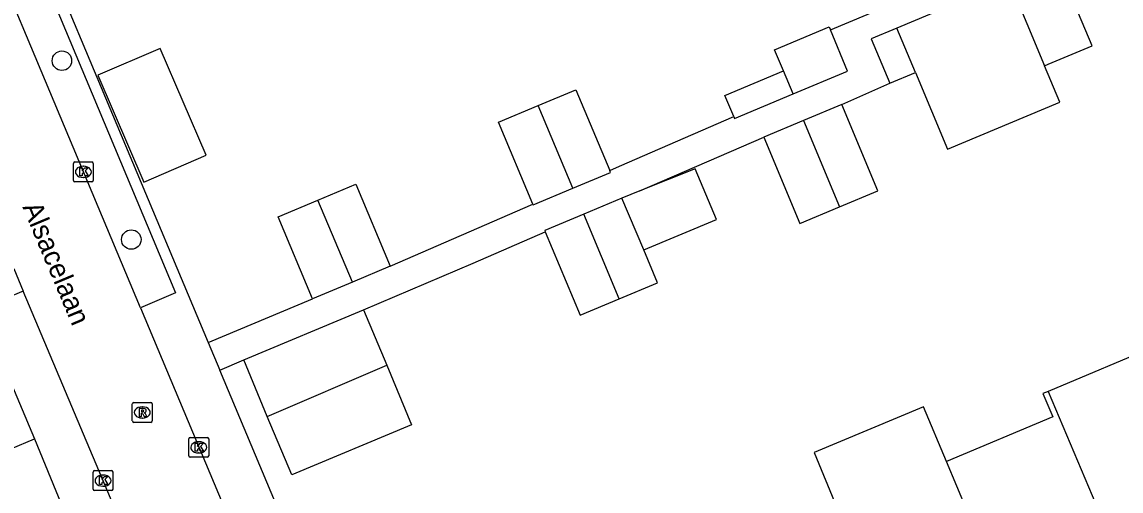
# Model space of a CAD drawing. Extents: x 157767 to 159171, y 387842 to 389425.
# Drawn here: x 158884.5 to 158939.7, y 388284.7 to 388308.2 of the extents above; entities that cross this region are included whole.
import ezdxf

# ---------------------------------------------------------------- set-up
doc = ezdxf.new("R2010")
doc.units = 0
for name, color, linetype in [('IMGEO_Boom', 7, 'Continuous'), ('IMGEO_Kolk', 7, 'Continuous'), ('IMGEO_Openbare_ruimte_label', 7, 'Continuous'), ('IMGEO_Pand', 7, 'Continuous'), ('IMGEO_Rijbaan_lokaal_open', 7, 'Continuous'), ('IMGEO_Rioolput', 7, 'Continuous'), ('IMGEO_Voetpad_open', 7, 'Continuous')]:
    doc.layers.add(name, color=color, linetype=linetype)

msp = doc.modelspace()

# ---------------------------------------------------------------- linework, layer by layer
at = {"layer": 'IMGEO_Boom'}
for centre in [(158886.479, 388306.281), (158889.962, 388297.308)]:
    msp.add_circle(centre, 0.489, dxfattribs=at)
at = {"layer": 'IMGEO_Kolk'}
for p, q in [((158887.054, 388300.278), (158887.054, 388301.13)), ((158887.129, 388301.204), (158887.981, 388301.204)), ((158887.542, 388300.984), (158887.567, 388300.984)), ((158888.055, 388301.13), (158888.055, 388300.278)), ((158887.565, 388300.424), (158887.54, 388300.424)), ((158887.981, 388300.204), (158887.129, 388300.204)), ((158892.847, 388286.46), (158892.847, 388287.312)), ((158892.922, 388287.386), (158893.774, 388287.386)), ((158893.335, 388287.166), (158893.36, 388287.166)), ((158893.848, 388287.312), (158893.848, 388286.46)), ((158893.358, 388286.606), (158893.333, 388286.606)), ((158893.774, 388286.386), (158892.922, 388286.386)), ((158888.042, 388284.789), (158888.042, 388285.641)), ((158888.117, 388285.715), (158888.969, 388285.715)), ((158888.53, 388285.495), (158888.555, 388285.495)), ((158889.043, 388285.641), (158889.043, 388284.789)), ((158888.553, 388284.935), (158888.528, 388284.935)), ((158888.969, 388284.715), (158888.117, 388284.715))]:
    msp.add_line(p, q, dxfattribs=at)
for points in [[(158887.054, 388300.278), (158887.054, 388301.13)], [(158887.129, 388301.204), (158887.981, 388301.204)], [(158887.375, 388300.904), (158887.498, 388300.904), (158887.498, 388300.753), (158887.628, 388300.904), (158887.792, 388300.904), (158887.646, 388300.753), (158887.799, 388300.504), (158887.647, 388300.504), (158887.562, 388300.668), (158887.498, 388300.601), (158887.498, 388300.504), (158887.375, 388300.504), (158887.375, 388300.904)], [(158888.055, 388301.13), (158888.055, 388300.278)], [(158887.981, 388300.204), (158887.129, 388300.204)], [(158892.847, 388286.46), (158892.847, 388287.312)], [(158892.922, 388287.386), (158893.774, 388287.386)], [(158893.168, 388287.086), (158893.291, 388287.086), (158893.291, 388286.935), (158893.421, 388287.086), (158893.585, 388287.086), (158893.439, 388286.935), (158893.592, 388286.686), (158893.44, 388286.686), (158893.355, 388286.85), (158893.291, 388286.783), (158893.291, 388286.686), (158893.168, 388286.686), (158893.168, 388287.086)], [(158893.848, 388287.312), (158893.848, 388286.46)], [(158893.774, 388286.386), (158892.922, 388286.386)], [(158888.042, 388284.789), (158888.042, 388285.641)], [(158888.117, 388285.715), (158888.969, 388285.715)], [(158888.363, 388285.415), (158888.486, 388285.415), (158888.486, 388285.264), (158888.616, 388285.415), (158888.78, 388285.415), (158888.634, 388285.264), (158888.787, 388285.015), (158888.635, 388285.015), (158888.55, 388285.179), (158888.486, 388285.112), (158888.486, 388285.015), (158888.363, 388285.015), (158888.363, 388285.415)], [(158889.043, 388285.641), (158889.043, 388284.789)], [(158888.969, 388284.715), (158888.117, 388284.715)]]:
    msp.add_lwpolyline(points, dxfattribs=at)
for centre, start, end in [((158887.131, 388301.128), 91.552, 178.448), ((158887.131, 388301.128), 91.552, 178.448), ((158887.979, 388301.128), 1.552, 88.448), ((158887.979, 388301.128), 1.552, 88.448), ((158887.131, 388300.28), 181.552, 268.448), ((158887.131, 388300.28), 181.552, 268.448), ((158887.979, 388300.28), 271.552, 358.448), ((158887.979, 388300.28), 271.552, 358.448), ((158892.924, 388287.31), 91.552, 178.448), ((158892.924, 388287.31), 91.552, 178.448), ((158893.772, 388287.31), 1.552, 88.448), ((158893.772, 388287.31), 1.552, 88.448), ((158892.924, 388286.462), 181.552, 268.448), ((158892.924, 388286.462), 181.552, 268.448), ((158893.772, 388286.462), 271.552, 358.448), ((158893.772, 388286.462), 271.552, 358.448), ((158888.119, 388285.639), 91.552, 178.448), ((158888.119, 388285.639), 91.552, 178.448), ((158888.967, 388285.639), 1.552, 88.448), ((158888.967, 388285.639), 1.552, 88.448), ((158888.119, 388284.791), 181.552, 268.448), ((158888.119, 388284.791), 181.552, 268.448), ((158888.967, 388284.791), 271.552, 358.448), ((158888.967, 388284.791), 271.552, 358.448)]:
    msp.add_arc(centre, 0.0765, start, end, dxfattribs=at)
for centre, major_axis, ratio, start_param, end_param in [((158887.541, 388300.704), (-0.387, 0.002), 0.722429, 4.712389, 7.853982), ((158887.566, 388300.704), (-0.39, 0.002), 0.717154, 1.570796, 4.712389), ((158893.334, 388286.886), (-0.387, 0.002), 0.722429, 4.712389, 7.853982), ((158893.359, 388286.886), (-0.39, 0.002), 0.717154, 1.570796, 4.712389), ((158888.529, 388285.215), (-0.387, 0.002), 0.722429, 4.712389, 7.853982), ((158888.554, 388285.215), (-0.39, 0.002), 0.717154, 1.570796, 4.712389)]:
    msp.add_ellipse(centre, major_axis=major_axis, ratio=ratio, start_param=start_param, end_param=end_param, dxfattribs=at)
at = {"layer": 'IMGEO_Pand'}
for points in [[(158935.815, 388306.03), (158935.99, 388306.103), (158938.199, 388307.027), (158936.419, 388311.28)], [(158934.036, 388310.282), (158928.398, 388307.923)], [(158934.036, 388310.282), (158935.815, 388306.03)], [(158922.702, 388305.775), (158922.262, 388306.827), (158925.004, 388307.974), (158925.064, 388307.831)], [(158923.187, 388304.617), (158925.929, 388305.764), (158925.064, 388307.831)], [(158928.398, 388307.923), (158927.106, 388307.383), (158928.041, 388305.15)], [(158929.332, 388305.69), (158928.398, 388307.923)], [(158893.717, 388301.537), (158891.417, 388306.897), (158888.29, 388305.555), (158890.591, 388300.195), (158893.717, 388301.537)], [(158920.208, 388303.484), (158919.763, 388304.545), (158922.702, 388305.775)], [(158923.187, 388304.617), (158922.702, 388305.775)], [(158929.332, 388305.69), (158930.939, 388301.849), (158936.578, 388304.208), (158935.815, 388306.03)], [(158928.041, 388305.15), (158929.332, 388305.69)], [(158910.394, 388304.035), (158912.289, 388304.828), (158913.986, 388300.773)], [(158920.208, 388303.484), (158920.248, 388303.387), (158923.187, 388304.617)], [(158910.118, 388299.087), (158908.398, 388303.199), (158910.394, 388304.035)], [(158912.134, 388299.88), (158910.394, 388304.035)], [(158925.641, 388304.085), (158923.721, 388303.282)], [(158925.52, 388298.948), (158927.453, 388299.757), (158925.641, 388304.085)], [(158923.721, 388303.282), (158921.721, 388302.445)], [(158923.721, 388303.282), (158925.52, 388298.948)], [(158921.721, 388302.445), (158923.533, 388298.116), (158925.52, 388298.948)], [(158915.688, 388296.79), (158919.346, 388298.321), (158918.282, 388300.863), (158915.494, 388299.747)], [(158912.134, 388299.88), (158914.028, 388300.673), (158913.986, 388300.773)], [(158899.336, 388299.286), (158901.233, 388300.08), (158902.954, 388295.966)], [(158910.118, 388299.087), (158910.136, 388299.044), (158912.134, 388299.88)], [(158915.494, 388299.747), (158914.6, 388299.389)], [(158899.058, 388294.336), (158897.337, 388298.45), (158899.336, 388299.286)], [(158901.062, 388295.175), (158899.336, 388299.286)], [(158914.6, 388299.389), (158912.677, 388298.584)], [(158915.688, 388296.79), (158914.6, 388299.389)], [(158912.677, 388298.584), (158910.718, 388297.764), (158910.749, 388297.691)], [(158914.454, 388294.34), (158912.677, 388298.584)], [(158910.749, 388297.691), (158912.494, 388293.52), (158914.454, 388294.34)], [(158914.454, 388294.34), (158916.376, 388295.145), (158915.688, 388296.79)], [(158902.954, 388295.966), (158901.062, 388295.175)], [(158901.062, 388295.175), (158899.058, 388294.336)], [(158895.608, 388291.269), (158901.625, 388293.786)], [(158901.625, 388293.786), (158902.785, 388291.013)], [(158941.637, 388292.054), (158935.995, 388289.694)], [(158896.792, 388288.439), (158895.608, 388291.269)], [(158902.785, 388291.013), (158904.037, 388288.021), (158898.02, 388285.504), (158896.792, 388288.439)], [(158896.792, 388288.439), (158902.785, 388291.013)], [(158935.995, 388289.694), (158935.735, 388289.585), (158936.227, 388288.408), (158930.89, 388286.175)], [(158935.995, 388289.694), (158939.126, 388282.299)], [(158930.89, 388286.175), (158929.74, 388288.92), (158924.254, 388286.621), (158925.388, 388283.874)], [(158934.004, 388278.741), (158930.89, 388286.175)]]:
    msp.add_lwpolyline(points, dxfattribs=at)
at = {"layer": 'IMGEO_Rijbaan_lokaal_open'}
for points in [[(158890.42, 388293.888), (158878.449, 388322.427)], [(158884.057, 388295.857), (158884.536, 388294.722)], [(158894.573, 388270.936), (158884.536, 388294.722)], [(158890.42, 388293.888), (158894.993, 388283.005)]]:
    msp.add_lwpolyline(points, dxfattribs=at)
at = {"layer": 'IMGEO_Rioolput'}
for p, q in [((158890.014, 388288.209), (158890.014, 388289.061)), ((158890.089, 388289.135), (158890.941, 388289.135)), ((158890.502, 388288.915), (158890.527, 388288.915)), ((158891.015, 388289.061), (158891.015, 388288.209)), ((158890.941, 388288.135), (158890.089, 388288.135)), ((158890.525, 388288.355), (158890.5, 388288.355))]:
    msp.add_line(p, q, dxfattribs=at)
for points in [[(158890.014, 388288.209), (158890.014, 388289.061)], [(158890.089, 388289.135), (158890.941, 388289.135)], [(158890.603, 388288.833), (158890.351, 388288.835), (158890.351, 388288.435)], [(158890.529, 388288.754), (158890.475, 388288.754), (158890.475, 388288.673)], [(158890.475, 388288.673), (158890.527, 388288.673)], [(158891.015, 388289.061), (158891.015, 388288.209)], [(158890.941, 388288.135), (158890.089, 388288.135)], [(158890.351, 388288.435), (158890.475, 388288.435), (158890.475, 388288.597), (158890.486, 388288.597)], [(158890.533, 388288.568), (158890.604, 388288.435), (158890.744, 388288.435), (158890.679, 388288.561)]]:
    msp.add_lwpolyline(points, dxfattribs=at)
for centre, radius, start, end in [((158890.091, 388289.059), 0.0765, 91.552, 178.448), ((158890.091, 388289.059), 0.0765, 91.552, 178.448), ((158890.511, 388288.862), 0.19, 274.7715, 282.9687), ((158890.535, 388288.658), 0.0964, 77.0061, 93.1865), ((158890.549, 388288.715), 0.0378, 276.6634, 79.6772), ((158890.602, 388288.723), 0.109, 350.3612, 89.416), ((158890.6, 388288.723), 0.112, 277.5842, 350.9817), ((158890.939, 388289.059), 0.0765, 1.552, 88.448), ((158890.939, 388289.059), 0.0765, 1.552, 88.448), ((158890.091, 388288.211), 0.0765, 181.552, 268.448), ((158890.091, 388288.211), 0.0765, 181.552, 268.448), ((158890.485, 388288.544), 0.0533, 26.0293, 88.6989), ((158890.584, 388288.508), 0.108, 29.5134, 73.7905), ((158890.939, 388288.211), 0.0765, 271.552, 358.448), ((158890.939, 388288.211), 0.0765, 271.552, 358.448)]:
    msp.add_arc(centre, radius, start, end, dxfattribs=at)
for centre, major_axis, ratio, start_param, end_param in [((158890.501, 388288.635), (-0.387, 0.002), 0.722429, 4.712389, 7.853982), ((158890.526, 388288.635), (-0.39, 0.002), 0.717154, 1.570796, 4.712389)]:
    msp.add_ellipse(centre, major_axis=major_axis, ratio=ratio, start_param=start_param, end_param=end_param, dxfattribs=at)
at = {"layer": 'IMGEO_Voetpad_open'}
for points in [[(158880.218, 388323.17), (158892.189, 388294.632), (158890.42, 388293.888)], [(158880.705, 388323.361), (158893.823, 388292.144)], [(158925.064, 388307.831), (158951.129, 388318.735)], [(158876.66, 388307.31), (158877.594, 388305.099), (158880.791, 388297.534), (158885.107, 388287.319)], [(158925.641, 388304.085), (158928.041, 388305.15)], [(158913.986, 388300.773), (158914.482, 388300.989), (158920.208, 388303.484)], [(158915.494, 388299.747), (158921.721, 388302.445)], [(158902.954, 388295.966), (158910.118, 388299.087)], [(158901.625, 388293.786), (158907.135, 388296.125), (158910.749, 388297.691)], [(158884.536, 388294.722), (158883.493, 388294.285), (158883.017, 388295.422), (158884.057, 388295.857)], [(158893.823, 388292.144), (158899.058, 388294.336)], [(158893.823, 388292.144), (158894.403, 388290.763)], [(158894.403, 388290.763), (158895.608, 388291.269)], [(158907.217, 388260.272), (158894.403, 388290.763)], [(158827.849, 388286.77), (158836.369, 388266.746), (158885.107, 388287.319)], [(158885.107, 388287.319), (158887.788, 388280.782)]]:
    msp.add_lwpolyline(points, dxfattribs=at)

# ---------------------------------------------------------------- texts
at = {"layer": 'IMGEO_Openbare_ruimte_label'}
msp.add_text('Alsacelaan', height=1, rotation=292.7697, dxfattribs=at).set_placement((158884.485, 388298.948))

doc.saveas('drawing.dxf')
